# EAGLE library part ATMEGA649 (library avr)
MICROCONTROLLER 64 Kbytes FLASH 4 Kbytes SRAM 2 Kbytes EEPROM USART 8-channel 10 bit ADC LCD Driver
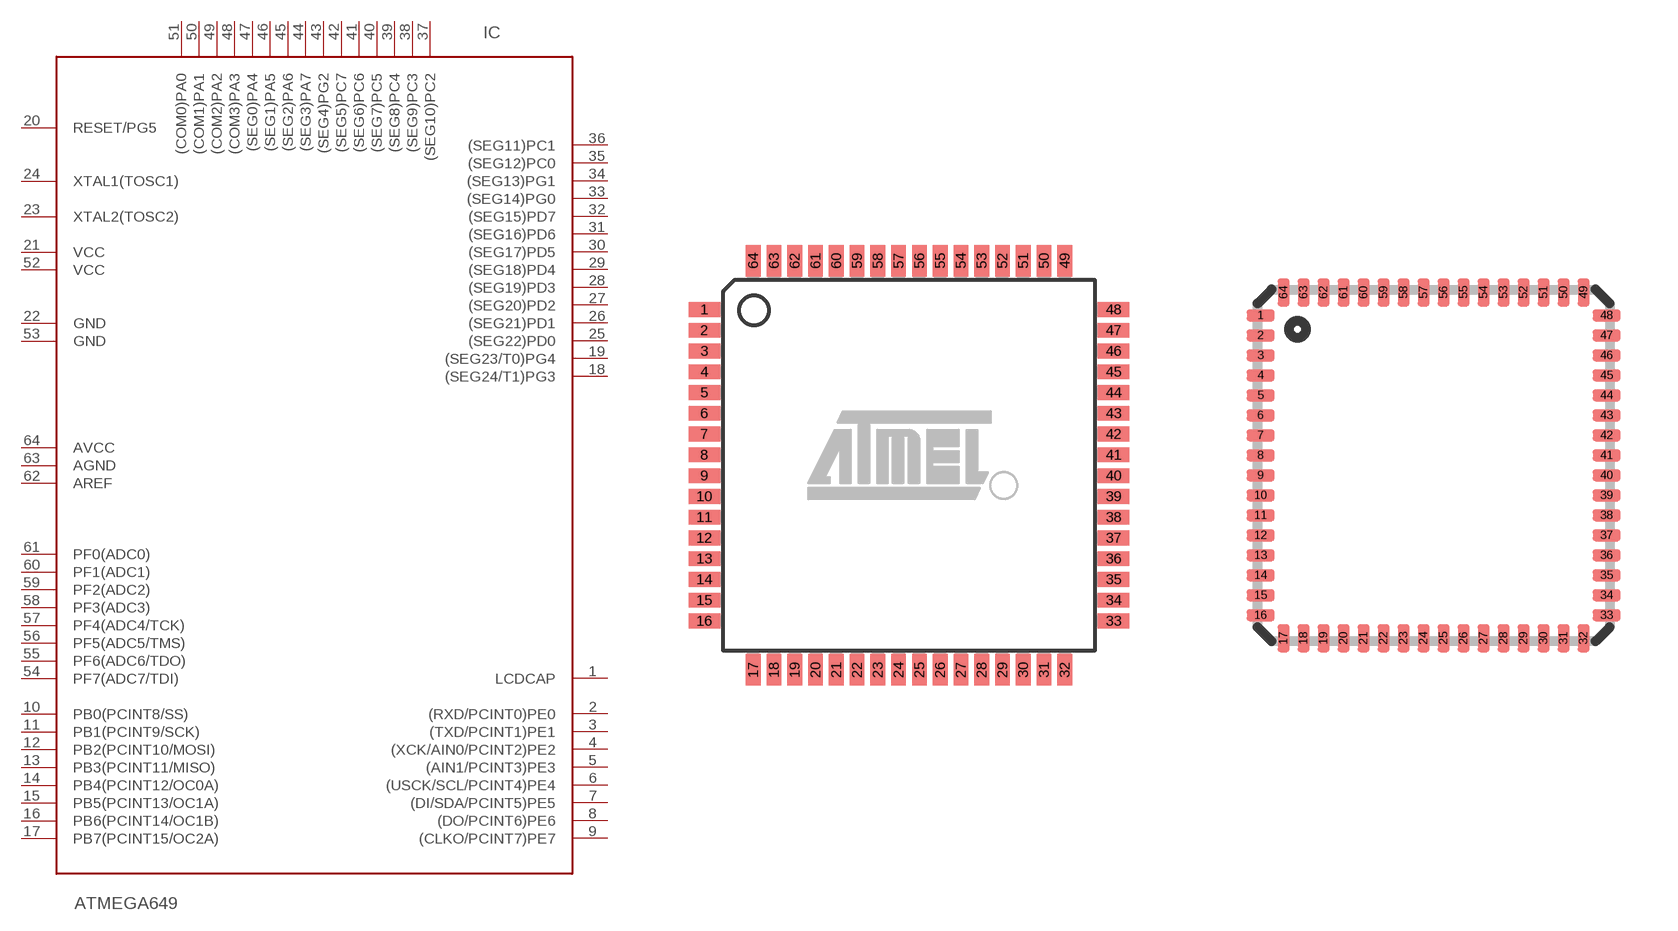
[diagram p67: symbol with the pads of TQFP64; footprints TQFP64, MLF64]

Designator prefix IC

## ATMEGA649-16A, ATMEGA649V-8A  [TQFP64]
1  LCDCAP
2  (RXD/PCINT0)PE0
3  (TXD/PCINT1)PE1
4  (XCK/AIN0/PCINT2)PE2
5  (AIN1/PCINT3)PE3
6  (USCK/SCL/PCINT4)PE4
7  (DI/SDA/PCINT5)PE5
8  (DO/PCINT6)PE6
9  (CLKO/PCINT7)PE7
10  PB0(PCINT8/SS)  nc
11  PB1(PCINT9/SCK)  nc
12  PB2(PCINT10/MOSI)  nc
13  PB3(PCINT11/MISO)  nc
14  PB4(PCINT12/OC0A)  nc
15  PB5(PCINT13/OC1A)  nc
16  PB6(PCINT14/OC1B)  nc
17  PB7(PCINT15/OC2A)
18  (SEG24/T1)PG3
19  (SEG23/T0)PG4
20  RESET/PG5
21  VCC
22  GND
23  XTAL2(TOSC2)
24  XTAL1(TOSC1)
25  (SEG22)PD0
26  (SEG21)PD1
27  (SEG20)PD2
28  (SEG19)PD3
29  (SEG18)PD4
30  (SEG17)PD5
31  (SEG16)PD6
32  (SEG15)PD7
33  (SEG14)PG0
34  (SEG13)PG1
35  (SEG12)PC0
36  (SEG11)PC1
37  (SEG10)PC2
38  (SEG9)PC3
39  (SEG8)PC4
40  (SEG7)PC5
41  (SEG6)PC6
42  (SEG5)PC7
43  (SEG4)PG2
44  (SEG3)PA7
45  (SEG2)PA6
46  (SEG1)PA5
47  (SEG0)PA4
48  (COM3)PA3
49  (COM2)PA2
50  (COM1)PA1
51  (COM0)PA0
52  VCC
53  GND
54  PF7(ADC7/TDI)  nc
55  PF6(ADC6/TDO)  nc
56  PF5(ADC5/TMS)  nc
57  PF4(ADC4/TCK)  nc
58  PF3(ADC3)  nc
59  PF2(ADC2)  nc
60  PF1(ADC1)  nc
61  PF0(ADC0)  nc
62  AREF  pwr
63  AGND  pwr
64  AVCC  pwr

## ATMEGA649-16M, ATMEGA649V-8M  [MLF64]
Pads as for TQFP64

## Footprint TQFP64 (pad centres in mm)
Thin Plasic Quad Flat Package
smd 1.194 x 0.559: 1 -7.76,5.905; 2 -7.76,5.118; 3 -7.76,4.331; 4 -7.76,3.543; 5 -7.76,2.756; 6 -7.76,1.968; 7 -7.76,1.181; 8 -7.76,0.394; 9 -7.76,-0.394; 10 -7.76,-1.181; 11 -7.76,-1.968; 12 -7.76,-2.756; 13 -7.76,-3.543; 14 -7.76,-4.331; 15 -7.76,-5.118; 16 -7.76,-5.905; 33 7.76,-5.905; 34 7.76,-5.118; 35 7.76,-4.331; 36 7.76,-3.543; 37 7.76,-2.756; 38 7.76,-1.968; 39 7.76,-1.181; 40 7.76,-0.394; 41 7.76,0.394; 42 7.76,1.181; 43 7.76,1.968; 44 7.76,2.756; 45 7.76,3.543; 46 7.76,4.331; 47 7.76,5.118; 48 7.76,5.905
smd 0.559 x 1.194: 17 -5.905,-7.76; 18 -5.118,-7.76; 19 -4.331,-7.76; 20 -3.543,-7.76; 21 -2.756,-7.76; 22 -1.968,-7.76; 23 -1.181,-7.76; 24 -0.394,-7.76; 25 0.394,-7.76; 26 1.181,-7.76; 27 1.968,-7.76; 28 2.756,-7.76; 29 3.543,-7.76; 30 4.331,-7.76; 31 5.118,-7.76; 32 5.905,-7.76; 49 5.905,7.76; 50 5.118,7.76; 51 4.331,7.76; 52 3.543,7.76; 53 2.756,7.76; 54 1.968,7.76; 55 1.181,7.76; 56 0.394,7.76; 57 -0.394,7.76; 58 -1.181,7.76; 59 -1.968,7.76; 60 -2.756,7.76; 61 -3.543,7.76; 62 -4.331,7.76; 63 -5.118,7.76; 64 -5.905,7.76

## Footprint MLF64 (pad centres in mm)
64M1 Micro Lead Frame package (MLF)
smd 0.7 x 0.3: 1 -4.325,3.75; 2 -4.325,3.25; 3 -4.325,2.75; 4 -4.325,2.25; 5 -4.325,1.75; 6 -4.325,1.25; 7 -4.325,0.75; 8 -4.325,0.25; 9 -4.325,-0.25; 10 -4.325,-0.75; 11 -4.325,-1.25; 12 -4.325,-1.75; 13 -4.325,-2.25; 14 -4.325,-2.75; 15 -4.325,-3.25; 16 -4.325,-3.75; 33 4.325,-3.75; 34 4.325,-3.25; 35 4.325,-2.75; 36 4.325,-2.25; 37 4.325,-1.75; 38 4.325,-1.25; 39 4.325,-0.75; 40 4.325,-0.25; 41 4.325,0.25; 42 4.325,0.75; 43 4.325,1.25; 44 4.325,1.75; 45 4.325,2.25; 46 4.325,2.75; 47 4.325,3.25; 48 4.325,3.75
smd 0.3 x 0.7: 17 -3.75,-4.325; 18 -3.25,-4.325; 19 -2.75,-4.325; 20 -2.25,-4.325; 21 -1.75,-4.325; 22 -1.25,-4.325; 23 -0.75,-4.325; 24 -0.25,-4.325; 25 0.25,-4.325; 26 0.75,-4.325; 27 1.25,-4.325; 28 1.75,-4.325; 29 2.25,-4.325; 30 2.75,-4.325; 31 3.25,-4.325; 32 3.75,-4.325; 49 3.75,4.325; 50 3.25,4.325; 51 2.75,4.325; 52 2.25,4.325; 53 1.75,4.325; 54 1.25,4.325; 55 0.75,4.325; 56 0.25,4.325; 57 -0.25,4.325; 58 -0.75,4.325; 59 -1.25,4.325; 60 -1.75,4.325; 61 -2.25,4.325; 62 -2.75,4.325; 63 -3.25,4.325; 64 -3.75,4.325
